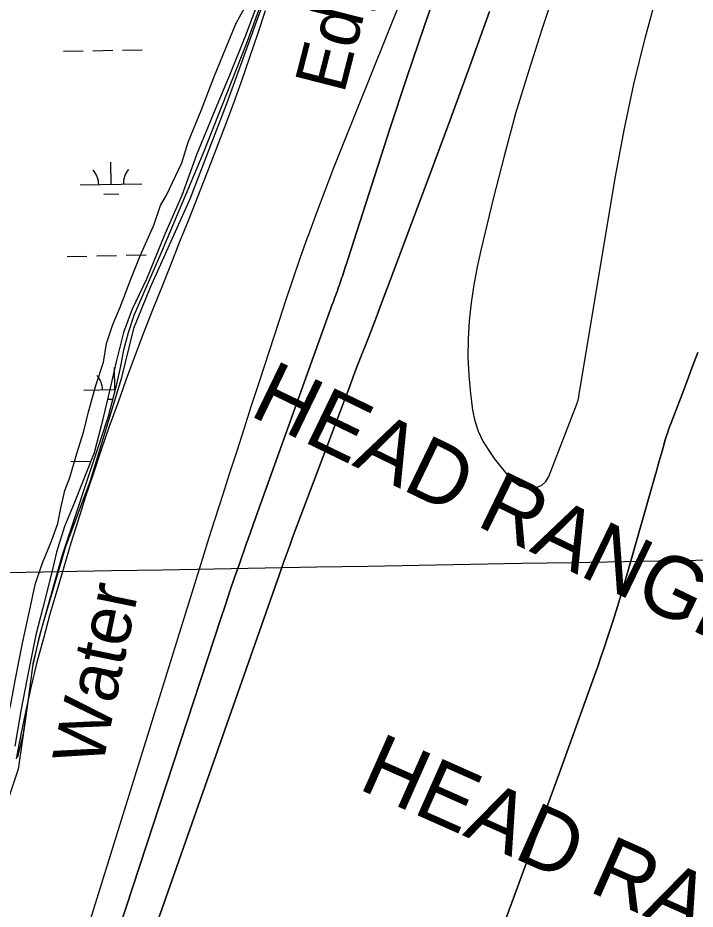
# Model space of a CAD drawing. Extents: x 3925854 to 3964121, y 224593 to 250589.
# Drawn here: x 3941743 to 3942841, y 235752 to 237197 of the extents above; entities that cross this region are included whole.
import ezdxf

# ---------------------------------------------------------------- set-up
doc = ezdxf.new("R2010")
doc.units = 0
for name, color, linetype in [('V-CHAN-NAID', 7, 'Continuous'), ('V-GRID-MAJR', 7, 'Continuous'), ('V-RIVR-EDGE', 7, 'Continuous'), ('V-RIVR-IDEN', 7, 'Continuous'), ('V-RIVR-JETY', 7, 'Continuous'), ('V-RRAP-FSHR', 7, 'Continuous'), ('V-TOPO-DPTH', 7, 'Continuous'), ('V-TOPO-MINR', 7, 'Continuous'), ('V-WETL-SWMP', 7, 'Continuous')]:
    doc.layers.add(name, color=color, linetype=linetype)

msp = doc.modelspace()

# ---------------------------------------------------------------- linework, layer by layer
at = {"layer": 'V-GRID-MAJR'}
msp.add_spline([(3930006.603, 236087.686), (3935327.129, 236182.494), (3940647.643, 236278.076), (3945968.142, 236374.431), (3951288.627, 236471.56), (3956609.098, 236569.464), (3961929.554, 236668.141), (3961929.555, 236668.141)], degree=3, dxfattribs=at)
at = {"layer": 'V-RIVR-EDGE'}
msp.add_lwpolyline([(3942136.294, 237208.987), (3942081.014, 237057.478), (3942021.638, 236902.897), (3941957.145, 236759.577), (3941930.528, 236693.036), (3941910.054, 236611.139), (3941859.892, 236446.321), (3941819.967, 236338.831), (3941781.066, 236206.773), (3941767.758, 236152.516), (3941755.473, 236064.477), (3941743.189, 235978.485), (3941712.477, 235887.374), (3941694.05, 235799.335), (3941675.624, 235740.983), (3941639.794, 235638.612), (3941614.201, 235556.715), (3941560.968, 235412.372), (3941530.256, 235329.451), (3941430.956, 235072.499), (3941325.514, 234830.903), (3941271.257, 234707.034), (3941208.811, 234552.453), (3941096.202, 234284.24)], dxfattribs=at)
at = {"layer": 'V-RIVR-JETY'}
for points in [[(3942142.972, 237250.389), (3942112.176, 237167.94), (3942086.717, 237104.964), (3942062.901, 237047.827), (3942032.228, 236974.757), (3942008.684, 236908.629), (3941981.278, 236846.066), (3941951.387, 236772.988), (3941928.075, 236724.442), (3941914.282, 236686.322), (3941902.317, 236638.801), (3941892.374, 236596.331), (3941878.3, 236537.111), (3941866.363, 236491.541), (3941834.42, 236411.063), (3941818.265, 236371.803), (3941805.211, 236330.548), (3941798.137, 236298.204), (3941783.298, 236240.166), (3941772.163, 236196.15), (3941757.522, 236123.649), (3941747.865, 236073.358), (3941738.117, 236016.037)], [(3941881.596, 236638.293), (3941886.3, 236668.716), (3941896.867, 236699.452), (3941908.578, 236727.827), (3941925.982, 236772.932), (3941940.949, 236811.035), (3941963.104, 236860.769), (3941974.079, 236892.673), (3941984.065, 236908.954), (3942008.606, 236961.782), (3942019.207, 236994.862), (3942040.215, 237046.566), (3942060.464, 237099.84), (3942081.063, 237149.983), (3942096.81, 237188.076), (3942114.027, 237219.116)], [(3941631.199, 235734.101), (3941648.357, 235790.152), (3941655.752, 235817.411), (3941676.875, 235877.711), (3941691.191, 235925.595), (3941703.528, 235971.939), (3941714.202, 236010.491), (3941724.567, 236055.299), (3941731.199, 236083.741), (3941739.171, 236125.064), (3941750.098, 236182.762), (3941761.734, 236234.98), (3941770.905, 236278.242), (3941782.292, 236311.7), (3941798.039, 236349.793), (3941807.775, 236376.632), (3941812.406, 236401.585), (3941819.041, 236430.419), (3941827.137, 236451.417), (3941838.598, 236490.347), (3941849.628, 236526.548), (3941857.468, 236557.71), (3941868.98, 236600.55), (3941881.596, 236638.293)]]:
    msp.add_lwpolyline(points, dxfattribs=at)
at = {"layer": 'V-RRAP-FSHR'}
msp.add_lwpolyline([(3942143.983, 237208.116), (3942131.116, 237170.242), (3942118.246, 237132.369), (3942105.194, 237094.558), (3942091.774, 237056.877), (3942077.884, 237019.368), (3942063.603, 236982.5), (3942049.323, 236944.641), (3942034.808, 236907.367), (3942019.973, 236870.223), (3942005.135, 236833.76), (3941990.297, 236795.929), (3941975.459, 236758.783), (3941960.812, 236721.562), (3941946.237, 236684.311), (3941931.905, 236646.968), (3941917.976, 236609.471), (3941904.709, 236571.966), (3941890.988, 236534.168), (3941877.903, 236496.368), (3941865.549, 236458.489), (3941852.661, 236420.457), (3941840.502, 236382.352), (3941828.823, 236344.949), (3941817.143, 236305.839), (3941805.721, 236267.506), (3941794.867, 236229.7), (3941784.111, 236190.508), (3941773.457, 236151.928), (3941764.128, 236113.37), (3941755.633, 236073.95), (3941747.714, 236034.743), (3941739.982, 235995.497)], dxfattribs=at)
at = {"layer": 'V-TOPO-DPTH'}
for points in [[(3942654.526, 237363.171), (3942592.369, 237177.768), (3942570.557, 237109.755), (3942549.946, 237041.396), (3942531.137, 236972.519), (3942513.529, 236903.298), (3942493.97, 236821.949), (3942487.669, 236793.039), (3942482.199, 236763.991), (3942477.974, 236734.735), (3942474.58, 236705.342), (3942472.81, 236675.862), (3942472.356, 236646.407), (3942473.877, 236616.987), (3942476.714, 236587.591), (3942480.205, 236560.856), (3942483.851, 236543.29), (3942489.13, 236526.369), (3942496.854, 236510.416), (3942506.21, 236495.108), (3942515.306, 236482.461), (3942521.514, 236474.075), (3942527.872, 236465.809), (3942534.456, 236457.72), (3942541.189, 236449.75), (3942541.309, 236449.613), (3942548.688, 236443.09), (3942556.746, 236438.046), (3942565.822, 236435.22), (3942575.578, 236433.872), (3942584.707, 236435.6), (3942592.639, 236439.083), (3942598.777, 236445.197), (3942603.718, 236453.065), (3942649.463, 236571.739), (3942650.362, 236574.314), (3942651.148, 236576.919), (3942651.767, 236579.569), (3942652.272, 236582.249), (3942652.698, 236584.951), (3942653.13, 236587.652), (3942653.571, 236590.352), (3942654.018, 236593.05), (3942712.02, 236939.16), (3942725.964, 237014.443), (3942741.61, 237089.341), (3942759.807, 237163.66), (3942779.706, 237237.593)], [(3942654.526, 237363.171), (3942592.369, 237177.768), (3942570.557, 237109.755), (3942549.946, 237041.396), (3942531.137, 236972.519), (3942513.529, 236903.298), (3942493.97, 236821.949), (3942487.669, 236793.039), (3942482.199, 236763.991), (3942477.974, 236734.735), (3942474.58, 236705.342), (3942472.81, 236675.862), (3942472.356, 236646.407), (3942473.877, 236616.987), (3942476.714, 236587.591), (3942480.205, 236560.856), (3942483.851, 236543.29), (3942489.13, 236526.369), (3942496.854, 236510.416), (3942506.21, 236495.108), (3942515.306, 236482.461), (3942521.514, 236474.075), (3942527.872, 236465.809), (3942534.456, 236457.72), (3942541.189, 236449.75), (3942541.309, 236449.613), (3942548.688, 236443.09), (3942556.746, 236438.046), (3942565.822, 236435.22), (3942575.578, 236433.872), (3942584.707, 236435.6), (3942592.639, 236439.083), (3942598.777, 236445.197), (3942603.718, 236453.065), (3942649.463, 236571.739), (3942650.362, 236574.314), (3942651.148, 236576.919), (3942651.767, 236579.569), (3942652.272, 236582.249), (3942652.698, 236584.951), (3942653.13, 236587.652), (3942653.571, 236590.352), (3942654.018, 236593.05), (3942712.02, 236939.16), (3942725.964, 237014.443), (3942741.61, 237089.341), (3942759.807, 237163.66), (3942779.706, 237237.593)], [(3941742.884, 235219.44), (3942071.889, 236222.687), (3942079.249, 236244.901), (3942086.698, 236267.085), (3942094.281, 236289.223), (3942101.954, 236311.33), (3942113.707, 236344.864), (3942115.577, 236350.18), (3942117.455, 236355.493), (3942119.344, 236360.803), (3942121.241, 236366.109), (3942123.145, 236371.413), (3942125.049, 236376.717), (3942126.955, 236382.021), (3942128.861, 236387.324), (3942252.644, 236731.678), (3942254.565, 236737.022), (3942256.488, 236742.365), (3942258.412, 236747.708), (3942260.337, 236753.05), (3942262.245, 236758.398), (3942264.128, 236763.755), (3942265.975, 236769.124), (3942267.799, 236774.502), (3942268.962, 236777.973), (3942271.337, 236785.097), (3942273.695, 236792.226), (3942276.028, 236799.363), (3942278.344, 236806.506), (3942346.174, 237016.908), (3942373.477, 237099.979), (3942401.408, 237182.834), (3942430.279, 237265.367)], [(3942507.685, 237206.978), (3942475.586, 237118.114), (3942443.002, 237029.426), (3942410.097, 236940.855), (3942341.159, 236756.836), (3942332.67, 236734.307), (3942324.123, 236711.799), (3942315.491, 236689.324), (3942306.802, 236666.871), (3942298.106, 236644.42), (3942289.46, 236621.951), (3942280.887, 236599.453), (3942272.362, 236576.937), (3942188.349, 236353.923), (3942183.562, 236341.085), (3942178.834, 236328.226), (3942174.193, 236315.335), (3942169.61, 236302.423), (3941781.655, 235197.506)], [(3941781.655, 235197.506), (3942169.61, 236302.423), (3942174.193, 236315.335), (3942178.834, 236328.226), (3942183.562, 236341.085), (3942188.349, 236353.923), (3942272.362, 236576.937), (3942280.887, 236599.453), (3942289.46, 236621.951), (3942298.106, 236644.42), (3942306.802, 236666.871), (3942315.491, 236689.324), (3942324.123, 236711.799), (3942332.67, 236734.307), (3942341.159, 236756.836), (3942410.097, 236940.855), (3942443.002, 237029.426), (3942475.586, 237118.114), (3942507.685, 237206.978)], [(3942845.35, 236654.229), (3942836.372, 236630.26), (3942827.3, 236606.327), (3942818.165, 236582.417), (3942801.939, 236540.194), (3942800.886, 236537.408), (3942799.854, 236534.614), (3942798.853, 236531.81), (3942797.872, 236528.997), (3942796.57, 236525.191), (3942794.994, 236520.457), (3942793.472, 236515.707), (3942792.031, 236510.931), (3942790.643, 236506.139), (3942787.291, 236494.186), (3942784.263, 236483.406), (3942781.226, 236472.628), (3942778.179, 236461.853), (3942775.124, 236451.081), (3942729.837, 236291.706), (3942722.664, 236267.106), (3942715.269, 236242.574), (3942707.538, 236218.146), (3942699.584, 236193.787), (3942693.334, 236175.081), (3942688.281, 236160.146), (3942683.152, 236145.238), (3942677.911, 236130.369), (3942672.594, 236115.526), (3942621.378, 235974.231), (3942590.28, 235888.803), (3942559.025, 235803.433), (3942527.536, 235718.149)], [(3942527.536, 235718.149), (3942559.025, 235803.433), (3942590.28, 235888.803), (3942621.378, 235974.231), (3942672.594, 236115.526), (3942677.911, 236130.369), (3942683.152, 236145.238), (3942688.281, 236160.146), (3942693.334, 236175.081), (3942699.584, 236193.787), (3942707.538, 236218.146), (3942715.269, 236242.574), (3942722.664, 236267.106), (3942729.837, 236291.706), (3942775.124, 236451.081), (3942778.179, 236461.853), (3942781.226, 236472.628), (3942784.263, 236483.406), (3942787.291, 236494.186), (3942790.643, 236506.139), (3942792.031, 236510.931), (3942793.472, 236515.707), (3942794.994, 236520.457), (3942796.57, 236525.191), (3942797.872, 236528.997), (3942798.853, 236531.81), (3942799.854, 236534.614), (3942800.886, 236537.408), (3942801.939, 236540.194), (3942818.165, 236582.417), (3942827.3, 236606.327), (3942836.372, 236630.26), (3942845.35, 236654.229)]]:
    msp.add_lwpolyline(points, dxfattribs=at)
at = {"layer": 'V-TOPO-MINR'}
for points in [[(3942654.526, 237363.171), (3942592.369, 237177.768), (3942570.557, 237109.755), (3942549.946, 237041.396), (3942531.137, 236972.519), (3942513.529, 236903.298), (3942493.97, 236821.949), (3942487.669, 236793.039), (3942482.199, 236763.991), (3942477.974, 236734.735), (3942474.58, 236705.342), (3942472.81, 236675.862), (3942472.356, 236646.407), (3942473.877, 236616.987), (3942476.714, 236587.591), (3942480.205, 236560.856), (3942483.851, 236543.29), (3942489.13, 236526.369), (3942496.854, 236510.416), (3942506.21, 236495.108), (3942515.306, 236482.461), (3942521.514, 236474.075), (3942527.872, 236465.809), (3942534.456, 236457.72), (3942541.189, 236449.75), (3942541.309, 236449.613), (3942548.688, 236443.09), (3942556.746, 236438.046), (3942565.822, 236435.22), (3942575.578, 236433.872), (3942584.707, 236435.6), (3942592.639, 236439.083), (3942598.777, 236445.197), (3942603.718, 236453.065), (3942649.463, 236571.739), (3942650.362, 236574.314), (3942651.148, 236576.919), (3942651.767, 236579.569), (3942652.272, 236582.249), (3942652.698, 236584.951), (3942653.13, 236587.652), (3942653.571, 236590.352), (3942654.018, 236593.05), (3942712.02, 236939.16), (3942725.964, 237014.443), (3942741.61, 237089.341), (3942759.807, 237163.66), (3942779.706, 237237.593)], [(3942411.836, 237345.361), (3942268.166, 236986.995), (3942254.19, 236951.612), (3942240.456, 236916.138), (3942227.084, 236880.525), (3942213.955, 236844.82), (3942212.112, 236839.73), (3942200.253, 236806.444), (3942188.618, 236773.08), (3942177.318, 236739.602), (3942166.241, 236706.047), (3942133.372, 236604.765), (3942121.265, 236567.416), (3942109.174, 236530.06), (3942097.11, 236492.697), (3942085.062, 236455.328), (3942078.218, 236434.078), (3942069.646, 236407.317), (3942061.13, 236380.538), (3942052.696, 236353.733), (3942044.318, 236326.911), (3941811.08, 235576.122)], [(3942430.279, 237265.367), (3942401.408, 237182.834), (3942373.477, 237099.979), (3942346.174, 237016.908), (3942278.344, 236806.506), (3942276.028, 236799.363), (3942273.695, 236792.226), (3942271.337, 236785.097), (3942268.962, 236777.973), (3942267.799, 236774.502), (3942265.975, 236769.124), (3942264.128, 236763.755), (3942262.245, 236758.398), (3942260.337, 236753.05), (3942258.412, 236747.708), (3942256.488, 236742.365), (3942254.565, 236737.022), (3942252.644, 236731.678), (3942128.861, 236387.324), (3942126.955, 236382.021), (3942125.049, 236376.717), (3942123.145, 236371.413), (3942121.241, 236366.109), (3942119.344, 236360.803), (3942117.455, 236355.493), (3942115.577, 236350.18), (3942113.707, 236344.864), (3942101.954, 236311.33), (3942094.281, 236289.223), (3942086.698, 236267.085), (3942079.249, 236244.901), (3942071.889, 236222.687), (3941742.884, 235219.44)], [(3942507.685, 237206.978), (3942475.586, 237118.114), (3942443.002, 237029.426), (3942410.097, 236940.855), (3942341.159, 236756.836), (3942332.67, 236734.307), (3942324.123, 236711.799), (3942315.491, 236689.324), (3942306.802, 236666.871), (3942298.106, 236644.42), (3942289.46, 236621.951), (3942280.887, 236599.453), (3942272.362, 236576.937), (3942188.349, 236353.923), (3942183.562, 236341.085), (3942178.834, 236328.226), (3942174.193, 236315.335), (3942169.61, 236302.423), (3941781.655, 235197.506)], [(3942845.35, 236654.229), (3942836.372, 236630.26), (3942827.3, 236606.327), (3942818.165, 236582.417), (3942801.939, 236540.194), (3942800.886, 236537.408), (3942799.854, 236534.614), (3942798.853, 236531.81), (3942797.872, 236528.997), (3942796.57, 236525.191), (3942794.994, 236520.457), (3942793.472, 236515.707), (3942792.031, 236510.931), (3942790.643, 236506.139), (3942787.291, 236494.186), (3942784.263, 236483.406), (3942781.226, 236472.628), (3942778.179, 236461.853), (3942775.124, 236451.081), (3942729.837, 236291.706), (3942722.664, 236267.106), (3942715.269, 236242.574), (3942707.538, 236218.146), (3942699.584, 236193.787), (3942693.334, 236175.081), (3942688.281, 236160.146), (3942683.152, 236145.238), (3942677.911, 236130.369), (3942672.594, 236115.526), (3942621.378, 235974.231), (3942590.28, 235888.803), (3942559.025, 235803.433), (3942527.536, 235718.149)]]:
    msp.add_lwpolyline(points, dxfattribs=at)
at = {"layer": 'V-WETL-SWMP'}
for p, q in [((3942113.752, 237154.45), (3942194.959, 237379.21)), ((3941816.627, 237142.521), (3941848.622, 237143.103)), ((3941864.619, 237143.393), (3941896.614, 237143.975)), ((3941912.611, 237144.266), (3941944.606, 237144.848)), ((3942043.684, 236977.64), (3942113.752, 237154.45)), ((3941975.188, 236815.183), (3942043.684, 236977.64)), ((3941893.972, 236926.648), (3941893.318, 236962.642)), ((3941843.981, 236925.739), (3941943.964, 236927.557)), ((3941882.255, 236911.002), (3941906.251, 236911.438)), ((3941822.675, 236809.901), (3941854.67, 236810.483)), ((3941870.667, 236810.773), (3941902.662, 236811.355)), ((3941918.659, 236811.646), (3941950.654, 236812.228)), ((3941931.476, 236714.788), (3941975.188, 236815.183)), ((3941922.258, 236686.715), (3941931.476, 236714.788)), ((3941914.419, 236658.347), (3941922.258, 236686.715)), ((3941909.645, 236631.874), (3941914.419, 236658.347)), ((3941900.02, 236594.028), (3941899.366, 236630.022)), ((3941902.874, 236600.728), (3941909.645, 236631.874)), ((3941850.029, 236593.119), (3941901.119, 236594.048)), ((3941889.774, 236550.87), (3941902.874, 236600.728)), ((3941888.303, 236578.382), (3941897.044, 236578.541)), ((3941877.384, 236512.888), (3941889.774, 236550.87)), ((3941814.625, 236324.371), (3941877.384, 236512.888)), ((3941828.723, 236477.281), (3941860.718, 236477.863)), ((3941778.065, 236193.832), (3941814.625, 236324.371)), ((3941767.19, 236145.05), (3941778.065, 236193.832)), ((3941758.914, 236083.794), (3941767.19, 236145.05)), ((3941751.935, 236036.895), (3941758.914, 236083.794)), ((3941742.578, 235998.32), (3941751.935, 236036.895))]:
    msp.add_line(p, q, dxfattribs=at)
for centre, start, end in [((3941838.73, 236926.119), 0.269879, 41.813537), ((3941949.197, 236928.127), 140.269876, 181.813534), ((3941844.778, 236593.499), 0.269879, 41.813537)]:
    msp.add_arc(centre, 35.246, start, end, dxfattribs=at)

# ---------------------------------------------------------------- texts
at = {"layer": 'V-CHAN-NAID'}
for s, rotation, p in [('HEAD RANGE FRONT (-1.5)', 334.125503, (3942116.053, 236553)), ('HEAD RANGE WEST', 336.034856, (3942292.578, 235947.449))]:
    msp.add_text(s, height=100, rotation=rotation, dxfattribs=at).set_placement(p)
at = {"layer": 'V-RIVR-IDEN'}
for s, rotation, p in [('Edge', 75.647103, (3942271.428, 237071.942)), ('Water', 78.321817, (3941879.482, 235980.447))]:
    msp.add_text(s, height=82.9998, rotation=rotation, dxfattribs=at).set_placement(p)

doc.saveas('drawing.dxf')
